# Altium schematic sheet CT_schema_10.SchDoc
size 254 x 194 mm
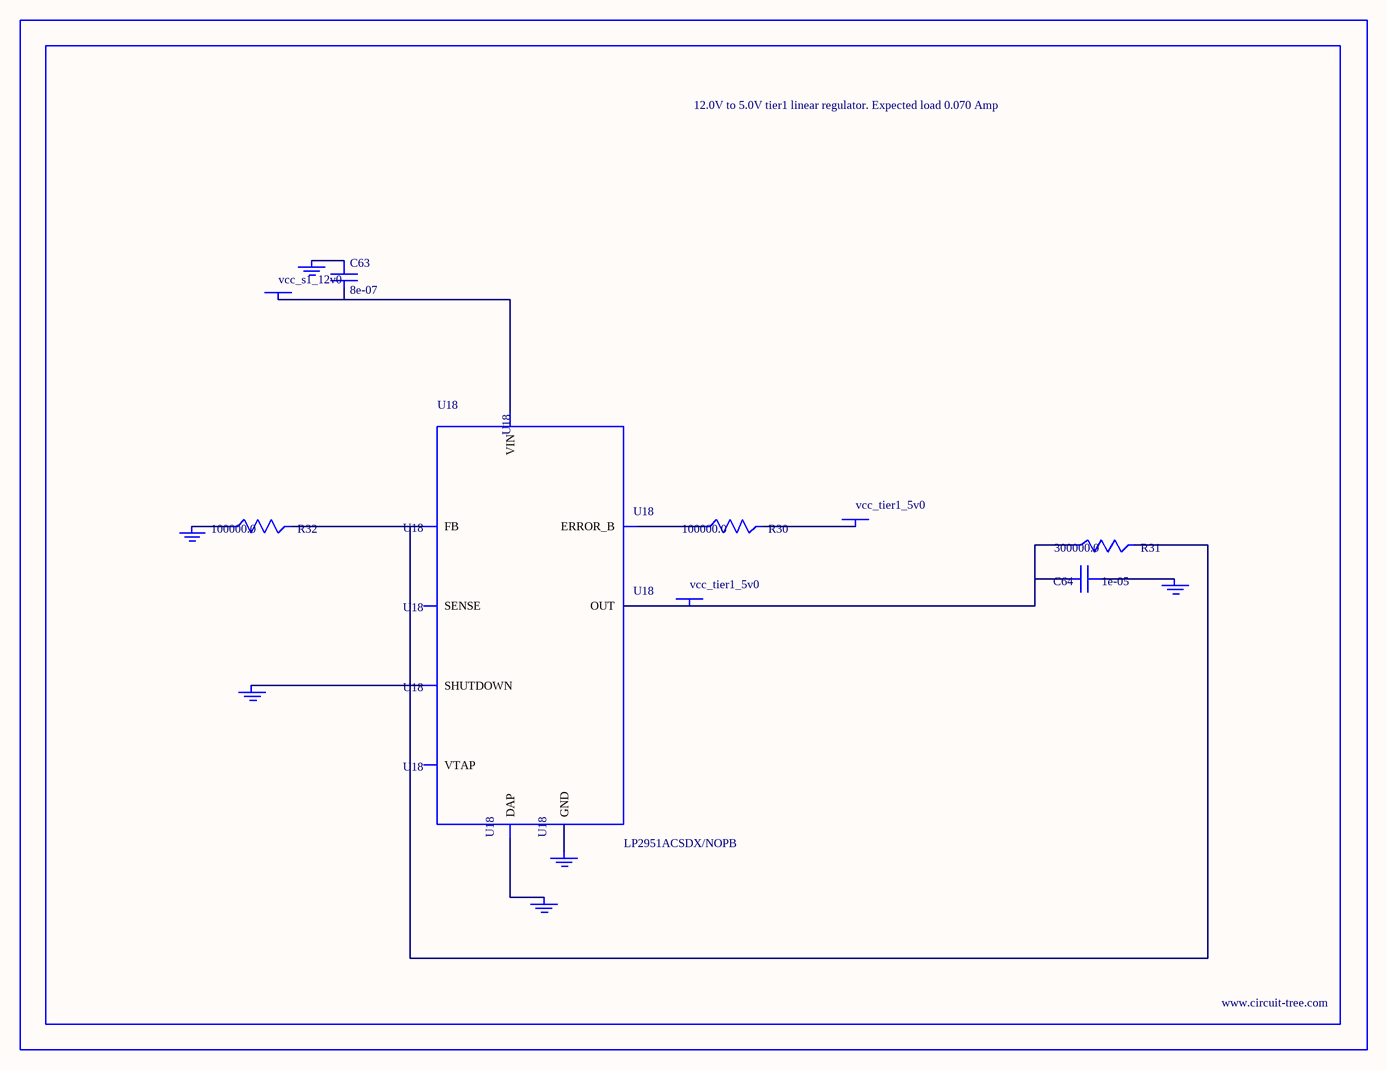
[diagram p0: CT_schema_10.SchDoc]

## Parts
BORDER9  (no value)
C63  8e-07  [R0603]
C64  1e-05  [C1210]
GND_INSTANCE_9_0  (no value)
GND_INSTANCE_9_1  (no value)
GND_INSTANCE_9_2  (no value)
GND_INSTANCE_9_3  (no value)
GND_INSTANCE_9_4  (no value)
GND_INSTANCE_9_5  (no value)
POWER_INSTANCE_9_0  vcc_tier1_5v0
POWER_INSTANCE_9_1  vcc_s1_12v0
POWER_INSTANCE_9_2  vcc_tier1_5v0
R30  100000.0  [R0603]
R31  300000.0  [R0603]
R32  100000.0  [R0603]
U18  LP2951ACSDX/NOPB  [WSON-8]

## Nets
NetC63_1: C63.1 GND_INSTANCE_9_3.0(GND)
NetC63_2: C63.2 POWER_INSTANCE_9_1.0(PWR) U18.8(VIN)
NetC64_1: C64.1 GND_INSTANCE_9_0.0(GND)
NetC64_2: C64.2 POWER_INSTANCE_9_2.0(PWR) R31.1 U18.1(OUT)
NetGND_INSTANCE_9_1_0: GND_INSTANCE_9_1.0(GND) U18.3(SHUTDOWN)
NetGND_INSTANCE_9_2_0: GND_INSTANCE_9_2.0(GND) R32.1
NetGND_INSTANCE_9_4_0: GND_INSTANCE_9_4.0(GND) U18.PAD(DAP)
NetGND_INSTANCE_9_5_0: GND_INSTANCE_9_5.0(GND) U18.4(GND)
NetPOWER_INSTANCE_9_0_0: POWER_INSTANCE_9_0.0(PWR) R30.2
NetR30_1: R30.1 U18.5(ERROR_B)
NetR31_2: R31.2 R32.2 U18.7(FB)

Not connected (* = marked no-connect by the designer): U18 2(SENSE) 6(VTAP)

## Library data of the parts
BORDER9 = BORDER_PAGE9
C63 = C63
C64 = GRM32DR61E106MA12L
GND_INSTANCE_9_0-GND_INSTANCE_9_5 = GND
POWER_INSTANCE_9_0-POWER_INSTANCE_9_2 = PWR
R30 R32 = RC0603JR-07100KL
R31 = RC0603JR-07300KL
